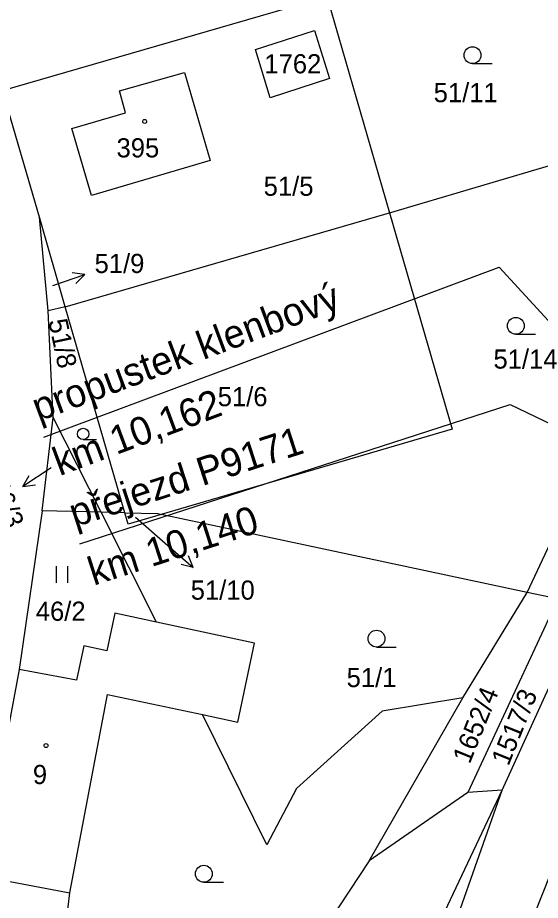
# Model space of a CAD drawing. Extents: x -553916 to -552953, y -1067470 to -1066637.
# Drawn here: x -553578.9 to -553532.5, y -1067025.6 to -1066947.3 of the extents above; entities that cross this region are included whole.
import ezdxf

# ---------------------------------------------------------------- set-up
doc = ezdxf.new("R2010")
doc.units = 0
for name, color, linetype in [('Hranice parcel', 7, 'Continuous'), ('Parcelní čísla', 7, 'Continuous'), ('Pop  PČ popisy', 7, 'Continuous'), ('Propustek', 7, 'Continuous'), ('Přejezd - štěrkové lože', 7, 'Continuous'), ('Značky budov', 7, 'Continuous'), ('Značky kultur', 7, 'Continuous')]:
    doc.layers.add(name, color=color, linetype=linetype)

msp = doc.modelspace()

# ---------------------------------------------------------------- linework, layer by layer
at = {"layer": 'Hranice parcel'}
for p, q in [((-553580.22, -1066953.72), (-553551.41, -1066945.38)), ((-553551.41, -1066945.38), (-553545.85, -1066964.59)), ((-553576.96, -1066964.99), (-553580.22, -1066953.72)), ((-553545.85, -1066964.59), (-553527.43, -1066959.15)), ((-553574.66, -1066972.93), (-553545.85, -1066964.59)), ((-553545.85, -1066964.59), (-553540.29, -1066983.8)), ((-553576.19, -1066973.29), (-553576.96, -1066964.99)), ((-553574.66, -1066972.93), (-553576.96, -1066964.99)), ((-553574.66, -1066972.93), (-553576.19, -1066973.29)), ((-553575.72, -1066982.77), (-553576.19, -1066973.29)), ((-553569.37, -1066991.22), (-553574.66, -1066972.93)), ((-553576.7, -1066991.04), (-553575.72, -1066982.77)), ((-553571.48, -1066991.17), (-553575.72, -1066982.77)), ((-553540.29, -1066983.8), (-553566.13, -1066991.36)), ((-553576.7, -1066991.04), (-553578.74, -1067005.13)), ((-553571.48, -1066991.17), (-553576.7, -1066991.04)), ((-553566.55, -1067000.93), (-553571.48, -1066991.17)), ((-553569.37, -1066991.22), (-553571.48, -1066991.17)), ((-553533.63, -1066998.28), (-553566.13, -1066991.36)), ((-553539.34, -1067007.65), (-553533.63, -1066998.28)), ((-553530.98, -1066998.99), (-553538.9, -1067016.05)), ((-553535.85, -1067015.85), (-553528.66, -1067000.03)), ((-553578.74, -1067005.13), (-553582.25, -1067023.44)), ((-553547.68, -1067022.12), (-553539.34, -1067007.65)), ((-553555.44, -1067071.33), (-553535.85, -1067015.85)), ((-553538.9, -1067016.05), (-553547.68, -1067022.12)), ((-553535.85, -1067015.85), (-553538.9, -1067016.05)), ((-553582.25, -1067023.44), (-553574.24, -1067024.96)), ((-553575.44, -1067034.44), (-553574.24, -1067024.96))]:
    msp.add_line(p, q, dxfattribs=at)
for points in [[(-553556.45, -1066954.37), (-553557.77, -1066950.08), (-553552.53, -1066948.42), (-553551.19, -1066952.66), (-553556.45, -1066954.37)], [(-553574.08, -1066957.11), (-553569.3, -1066955.7), (-553569.85, -1066953.76), (-553564.08, -1066952.14), (-553561.8, -1066959.96), (-553572.32, -1066963.04), (-553574.08, -1066957.11)], [(-553533.63, -1066998.28), (-553526.12, -1066982.3), (-553521.68, -1066973.05)], [(-553569.37, -1066991.22), (-553566.45, -1066991.29), (-553566.13, -1066991.36)], [(-553566.13, -1066991.36), (-553569.08, -1066992.22), (-553569.37, -1066991.22)], [(-553515.43, -1066991.08), (-553526.38, -1067010.19), (-553539.65, -1067043.59), (-553548.33, -1067069.03)], [(-553530.98, -1066998.99), (-553531.64, -1066998.7), (-553533.63, -1066998.28)], [(-553566.55, -1067000.93), (-553570.25, -1067000.14), (-553570.96, -1067003.47), (-553573.01, -1067003.03), (-553573.66, -1067006.09), (-553578.74, -1067005.13)], [(-553562.48, -1067009.13), (-553559.34, -1067009.8), (-553557.85, -1067002.78), (-553566.55, -1067000.93)], [(-553574.24, -1067024.96), (-553570.9, -1067007.35), (-553562.48, -1067009.13)], [(-553539.34, -1067007.65), (-553546.5, -1067008.84), (-553554.13, -1067015.7), (-553556.77, -1067020.68), (-553562.48, -1067009.13)], [(-553547.23, -1067042.51), (-553544.77, -1067034.69), (-553535.85, -1067015.85)], [(-553547.68, -1067022.12), (-553553.91, -1067031.58), (-553557.59, -1067038.38)]]:
    msp.add_lwpolyline(points, dxfattribs=at)
at = {"layer": 'Pop  PČ popisy'}
for p, q in [((-553575.77, -1066971.03), (-553572.933, -1066970.053)), ((-553572.933, -1066970.053), (-553574.042, -1066969.906)), ((-553572.933, -1066970.053), (-553573.716, -1066970.852)), ((-553575.91, -1066987.23), (-553578.418, -1066988.878)), ((-553578.418, -1066988.878), (-553577.856, -1066987.91)), ((-553578.418, -1066988.878), (-553577.306, -1066988.747)), ((-553568.43, -1066991.61), (-553565.55, -1066994.11)), ((-553565.55, -1066994.11), (-553563.285, -1066996.079)), ((-553563.285, -1066996.079), (-553563.712, -1066995.044)), ((-553563.285, -1066996.079), (-553564.369, -1066995.8))]:
    msp.add_line(p, q, dxfattribs=at)
at = {"layer": 'Propustek'}
msp.add_lwpolyline([(-553576.56, -1066984.514), (-553536.119, -1066969.402), (-553529.408, -1066976.709), (-553517.537, -1066972.276)], dxfattribs=at)
at = {"layer": 'Přejezd - štěrkové lože'}
msp.add_lwpolyline([(-553573.367, -1066993.961), (-553535.151, -1066981.6), (-553526.82, -1066985.587), (-553514.291, -1066981.32)], dxfattribs=at)
at = {"layer": 'Značky budov'}
for centre in [(-553567.607, -1066956.479), (-553576.367, -1067011.879)]:
    msp.add_circle(centre, 0.175, dxfattribs=at)
at = {"layer": 'Značky kultur'}
for p, q in [((-553538.493, -1066951.35), (-553536.743, -1066951.35)), ((-553534.638, -1066975.37), (-553532.888, -1066975.37)), ((-553573.07, -1066984.723), (-553571.898, -1066984.723)), ((-553575.423, -1066997.446), (-553575.423, -1066995.946)), ((-553574.422, -1066997.446), (-553574.422, -1066995.946)), ((-553547.013, -1067003.14), (-553545.263, -1067003.14)), ((-553562.353, -1067024.01), (-553560.603, -1067024.01))]:
    msp.add_line(p, q, dxfattribs=at)
for centre, radius in [((-553538.493, -1066950.6), 0.75), ((-553534.638, -1066974.62), 0.75), ((-553573.07, -1066984.22), 0.502), ((-553547.013, -1067002.39), 0.75), ((-553562.353, -1067023.26), 0.75)]:
    msp.add_circle(centre, radius, dxfattribs=at)

# ---------------------------------------------------------------- texts
at = {"layer": 'Parcelní čísla'}
for s, p in [('1762', (-553556.976, -1066952.208)), ('51/11', (-553541.938, -1066954.769)), ('395', (-553570.105, -1066959.67)), ('51/5', (-553557.039, -1066963.08)), ('51/9', (-553572.055, -1066969.934)), ('51/14', (-553536.628, -1066978.42)), ('51/6', (-553561.119, -1066981.759)), ('51/10', (-553563.518, -1066998.928)), ('46/2', (-553577.277, -1067000.8)), ('51/1', (-553549.669, -1067006.69)), ('9', (-553577.536, -1067015.3))]:
    msp.add_text(s, height=1.7, dxfattribs=at).set_placement(p)
for s, rotation, p in [('51/8', 282, (-553576.179, -1066974.183)), ('46/3', 291, (-553581.434, -1066988.581)), ('1652/4', 68, (-553538.741, -1067013.58)), ('1517/3', 68, (-553535.299, -1067013.759))]:
    msp.add_text(s, height=1.7, rotation=rotation, dxfattribs=at).set_placement(p)
at = {"layer": 'Propustek'}
for s, p in [('propustek klenbový', (-553577.034, -1066983.13)), ('km 10,162', (-553575.169, -1066987.971))]:
    msp.add_text(s, height=2.5, rotation=20.48994, dxfattribs=at).set_placement(p)
at = {"layer": 'Přejezd - štěrkové lože'}
for s, p in [('přejezd P9171', (-553573.821, -1066992.515)), ('km 10,140', (-553572.143, -1066997.703))]:
    msp.add_text(s, height=2.5, rotation=17.92384, dxfattribs=at).set_placement(p)

doc.saveas('drawing.dxf')
